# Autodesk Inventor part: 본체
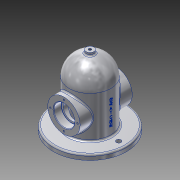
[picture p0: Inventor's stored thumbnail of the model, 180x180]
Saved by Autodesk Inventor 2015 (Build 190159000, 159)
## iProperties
Created: 2019-11
Part Number: 본체
Material: 알루미늄 6061
Document SubType Name: Modeling
Designer: 1010101
Density: 2.7 g/cm^3
Appearance: 알루미늄 - 평지
Mass: 1106.12 g
Surface Area: 883.272 cm^2
Volume: 409.676 cm^3
Author: 1010101
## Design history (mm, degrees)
sketch "스케치1"
  geometry: C1 r 70 at (0, 0); 1 further point
  constraints: 1 centre point, 1 coincident
  dimensions: "d0" = 140 diameter of C1
extrude "돌출1" new body sketch "스케치1" distance "d1" = 10; taper "d2" = 0 deg
sketch "스케치2"
  geometry: C1 r 70 at (0, 0) reference; C2 r 40 at (0, 0)
  constraints: 1 centre point, 1 coincident
  dimensions: "d3" = 80 diameter of C2
extrude "돌출2" join sketch "스케치2" distance "d4" = 80; taper "d5" = 0 deg
sketch "스케치4"
  geometry: L1 (70, 10)-(70, 0) reference; L2 (70, 0)-(-70, 0) reference; L3 (-70, 0)-(-70, 10) reference; L4 (-70, 10)-(-40, 10) reference; L5 (-40, 10)-(-40, 90) reference; L6 (-40, 90)-(40, 90) reference; L7 (40, 90)-(40, 10) reference; L8 (40, 10)-(70, 10) reference; A1 r 40 centre (0, 90) between (40, 90) and (-40, 90); 1 further point
  constraints: 2 end point, 2 point on circle, 1 centre point, 1 midpoint
revolve "회전1" sketch "스케치4" stored, may be unused: angle "d8" = 90 deg
node "작업 평면1"
sketch "스케치5"
  geometry: L1 (-70, 0)-(70, 0) reference; C1 r 31 at (0, 50); 2 further points
  constraints: 1 centre point, 1 coincident, 1 vertical alignment
  dimensions: "d10" = 50 distance from line of point (0, 50) L1; "d11" = 62 diameter of C1
extrude "돌출3" join sketch "스케치5" stored distance "d12" = 80; taper "d13" = 0 deg
sketch "스케치6"
  geometry: C1 r 31 at (0, 0) reference; C2 r 20 at (0, 0); 1 further point
  constraints: 1 centre point, 1 coincident
  dimensions: "d14" = 40 diameter of C2
extrude "돌출4" cut sketch "스케치6" distance "d15" = 15; taper "d16" = 0 deg
sketch "스케치7"
  geometry: C1 r 20 at (0, 0) reference; C2 r 16.5 at (0, 0); 1 further point
  constraints: 1 centre point, 1 coincident
  dimensions: "d17" = 33 diameter of C2
extrude "돌출5" cut sketch "스케치7" distance "d18" = 35; taper "d19" = 0 deg
sketch "스케치8"
  geometry: C1 r 20 at (0, 0) reference; 2 further points
  constraints: 1 vertical alignment
  dimensions: "d20" = 26 distance of C1.centre point (0, 26)
hole "구멍1" sketch "스케치8" at (0, 26) diameter "d21" = 3.242; stored, may be unused: countersink angle "d25" = 90 deg, drill point angle "d27" = 118 deg; dims "d22" = 8, "d23" = 4, "d24" = 2, "d26" = 10
sketch "스케치9"
  geometry: C1 r 70 at (0, 0) reference; C2 r 30 at (0, 0)
  constraints: 1 centre point, 1 coincident
  dimensions: "d31" = 60 diameter of C2
extrude "돌출6" cut sketch "스케치9" distance "d32" = 90; taper "d33" = 0 deg
sketch "스케치10"
  geometry: L1 (-50, 81)-(-40, 81) reference; L2 (-40, 81)-(-40, 90) reference; L3 (40, 90)-(40, 81) reference; L4 (40, 81)-(50, 81) reference; L5 (50, 81)-(50, 77.621) reference; L6 (50, 77.621)-(40, 77.621) reference; L7 (40, 77.621)-(39.026, 76) reference; L8 (39.026, 76)-(40, 74.379) reference; L9 (40, 74.379)-(50, 74.379) reference; L10 (50, 74.379)-(50, 70) reference; L11 (50, 70)-(35, 70) reference; L12 (35, 70)-(35, 66.5) reference; L13 (35, 66.5)-(30, 66.5) reference; L14 (30, 66.5)-(30, 90) reference; L15 (30, 90)-(-30, 90) reference; L16 (-30, 90)-(-30, 66.5) reference; L17 (-30, 66.5)-(-35, 66.5) reference; L18 (-35, 66.5)-(-35, 70) reference; L19 (-35, 70)-(-50, 70) reference; L20 (-50, 70)-(-50, 74.379) reference; L21 (-50, 74.379)-(-40, 74.379) reference; L22 (-40, 74.379)-(-39.026, 76) reference; L23 (-39.026, 76)-(-40, 77.621) reference; L24 (-40, 77.621)-(-50, 77.621) reference; L25 (-50, 77.621)-(-50, 81) reference; L26 (-70, 0)-(-70, 10) reference; L27 (-70, 10)-(-40, 10) reference; L28 (-40, 10)-(-40, 19) reference; L29 (-40, 19)-(-50, 19) reference; L30 (-50, 19)-(-50, 22.379) reference; L31 (-50, 22.379)-(-40, 22.379) reference; L32 (-40, 22.379)-(-39.026, 24) reference; L33 (-39.026, 24)-(-40, 25.621) reference; L34 (-40, 25.621)-(-50, 25.621) reference; L35 (-50, 25.621)-(-50, 30) reference; L36 (-50, 30)-(-35, 30) reference; L37 (-35, 30)-(-35, 33.5) reference; L38 (-35, 33.5)-(-30, 33.5) reference; L39 (-30, 33.5)-(-30, 0) reference; L40 (-30, 0)-(-70, 0) reference; L41 (70, 10)-(70, 0) reference; L42 (70, 0)-(30, 0) reference; L43 (30, 0)-(30, 33.5) reference; L44 (30, 33.5)-(35, 33.5) reference; L45 (35, 33.5)-(35, 30) reference; L46 (35, 30)-(50, 30) reference; L47 (50, 30)-(50, 25.621) reference; L48 (50, 25.621)-(40, 25.621) reference; L49 (40, 25.621)-(39.026, 24) reference; L50 (39.026, 24)-(40, 22.379) reference; L51 (40, 22.379)-(50, 22.379) reference; L52 (50, 22.379)-(50, 19) reference; L53 (50, 19)-(40, 19) reference; L54 (40, 19)-(40, 10) reference; L55 (40, 10)-(70, 10) reference; A1 r 40 centre (0, 90) between (40, 90) and (-40, 90) reference; A2 r 30 centre (0, 90) between (30, 90) and (-30, 90); 1 further point
  constraints: 2 end point, 2 point on circle, 1 centre point, 1 coincident
revolve "회전2" sketch "스케치10" stored, may be unused: angle "d35" = 90 deg
fillet "모깎기1" dims "d36" = 0.3
chamfer "모따기1" distance "d37" = 1; stored, may be unused: second distance "d38" = 2, angle "d39" = 45 deg
fillet "모깎기2" dims "d40" = 3
fillet "모깎기3" dims "d41" = 3
node "작업 평면2"
sketch "스케치11"
  geometry: C1 r 7.5 at (0, 0); 1 further point
  constraints: 1 centre point, 1 coincident
  dimensions: "d43" = 15 diameter of C1
extrude "돌출7" join sketch "스케치11" stored distance "d44" = 15 (= d43); taper "d45" = 0 deg
fillet "모깎기4" dims "d46" = 3
sketch "스케치12"
  geometry: C1 r 7.5 at (0, 0) reference
hole "구멍2" sketch "스케치12" at (0, 0) diameter "d47" = 5.188; stored, may be unused: countersink angle "d51" = 90 deg, drill point angle "d53" = 118 deg; dims "d48" = 12, "d49" = 4, "d50" = 2, "d52" = 40
node "작업 평면3"
sketch "스케치13"
  geometry: L1 (30, 0)-(-30, 0) reference; 2 further points
  constraints: 1 vertical alignment, 1 other
  dimensions: "d55" = 50 distance from line of L1 point (0, 50)
feature "엠보싱1" sketch "스케치13" dims "d10" = 50, "d11" = 62, "d56" = 0.5, "d57" = 0
sketch "스케치15"
  geometry: C1 r 30 at (0, 0) reference; 2 further points
  constraints: 2 horizontal alignment
  dimensions: "d61" = 55 distance of C1.centre point (-55, 0); "d62" = 55 distance of C1.centre point (55, 0)
hole "구멍3" sketch "스케치15" at (-55, 0), (55, 0) diameter "d63" = 9; stored, may be unused: countersink angle "d67" = 90 deg, drill point angle "d69" = 0 deg; dims "d64" = 12, "d65" = 4, "d66" = 2, "d68" = 40
node "솔리드1"
pattern_circular "원형 패턴1" dims angle "d29" = 360 deg
mirror "대칭2"
node "절단 모서리 투영1"
node "절단 모서리 투영2"
other parameters: "d42" = 135
